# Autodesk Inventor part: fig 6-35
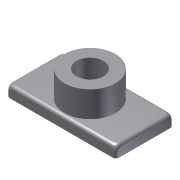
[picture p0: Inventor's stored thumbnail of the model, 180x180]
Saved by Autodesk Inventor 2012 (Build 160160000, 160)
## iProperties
Created: 2004-05
Part Number: fig 6-35
Document SubType Name: Modeling
Designer: CADCIM Technologies
Manufacturer: Standard
Standards Organization: Custom
Density: 1 g/cm^3
Material: Default
Author: CADCIM Technologies
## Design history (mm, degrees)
sketch "Sketch1"
  geometry: L1 (-39.276, -18.692)-(33.721, -18.692); L2 (33.721, -18.692)-(33.721, 19.728); L3 (33.721, 19.728)-(-39.276, 19.728); L4 (-39.276, 19.728)-(-39.276, -18.692)
  constraints: 8 end point, 2 parallel, 1 horizontal, 1 perpendicular
extrude "Extrusion1" new body sketch "Sketch1" distance "d0" = 7.5; taper "d1" = 0 deg
sketch "Sketch2"
  geometry: C1 r 17 at (-2.778, 0.518)
  constraints: 1 centre point
  dimensions: "d16" = 34 diameter of C1
extrude "Extrusion2" join sketch "Sketch2" distance "d3" = 17.25; taper "d4" = 0 deg
hole "Hole1" diameter "d8" = 18; stored, may be unused: countersink angle "d12" = 90 deg, drill point angle "d14" = 118 deg; dims "d6" = 10, "d7" = 10, "d9" = 6, "d10" = 4, "d11" = 2, "d13" = 8
fillet "Fillet4" dims "d17" = 2
body "Solid1"
